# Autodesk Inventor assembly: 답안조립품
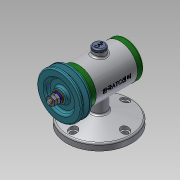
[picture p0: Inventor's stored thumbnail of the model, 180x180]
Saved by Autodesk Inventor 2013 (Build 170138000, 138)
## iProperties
Created: 2018-12
Part Number: 답안조립품
Document SubType Name: Assembly
Designer: Administrator
Author: Administrator
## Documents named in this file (15)
- C:\Users\Administrator\Desktop\481207V1032\답안조립품.iam
- C:\Users\Administrator\Desktop\481207V1032\본체.ipt
- C:\Users\Administrator\Desktop\481207V1032\V벨트풀리.ipt
- C:\Users\Administrator\Desktop\481207V1032\고무캡.ipt
- C:\Users\Administrator\Desktop\481207V1032\너트 M8.ipt
- 너트 M8.ipt
- C:\Users\Administrator\Desktop\481207V1032\뒤커버.ipt
- C:\Users\Administrator\Desktop\481207V1032\베어링 15 x 32 x 9.ipt
- C:\Users\Administrator\Desktop\481207V1032\볼트 M4 x 12.ipt
- C:\Users\Administrator\Desktop\481207V1032\스프링와셔 8.ipt
- C:\Users\Administrator\Desktop\481207V1032\앞커버.ipt
- C:\Users\Administrator\Desktop\481207V1032\오일 실 15 25 7.ipt
- C:\Users\Administrator\Desktop\481207V1032\와셔 8x17.ipt
- C:\Users\Administrator\Desktop\481207V1032\축.ipt
- C:\Users\Administrator\Desktop\481207V1032\키 3 x 3 x 12.ipt
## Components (2 placed, 2 different names)
1. V벨트풀리:1
2. 고무캡:1 — 각도:2
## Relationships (1: Angle 1)
- 각도:2 [Angle]: 고무캡:1
